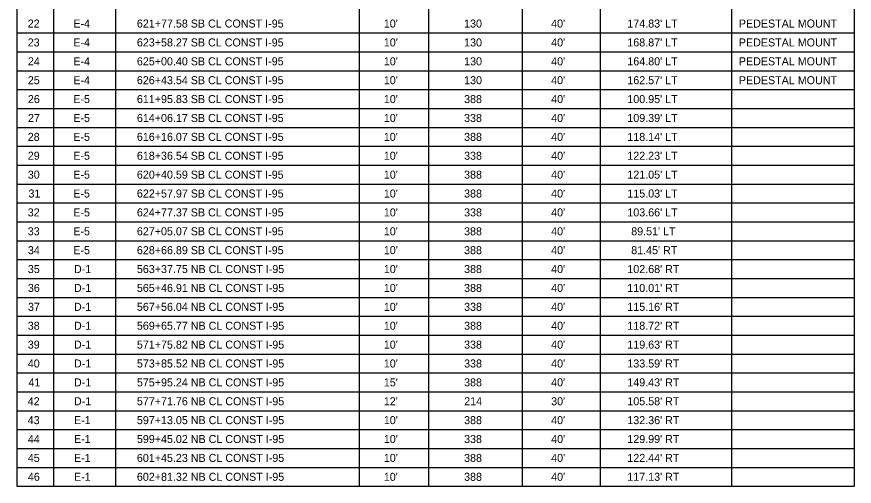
# Model space of a CAD drawing. Extents: x -818.1 to -802.4, y -2221.2 to -2187.7.
# Drawn here: x -817.38 to -810.06, y -2195.94 to -2191.84 of the extents above; entities that cross this region are included whole.
import ezdxf

# ---------------------------------------------------------------- set-up
doc = ezdxf.new("R2010")
doc.units = 0
for name, color, linetype in [('PlotBorder_dp', 7, 'Continuous'), ('SheetBorder_dp', 7, 'Continuous'), ('SheetLines_dp', 7, 'Continuous'), ('TextMinor', 7, 'Continuous')]:
    doc.layers.add(name, color=color, linetype=linetype)

msp = doc.modelspace()

# ---------------------------------------------------------------- linework, layer by layer
at = {"layer": 'PlotBorder_dp'}
for p, q in [((-817.0539, -2188.0217), (-817.0539, -2195.9417)), ((-817.0539, -2188.0217), (-817.0539, -2195.9417)), ((-816.5139, -2188.0217), (-816.5139, -2195.9417)), ((-816.5139, -2188.0217), (-816.5139, -2195.9417)), ((-814.3839, -2188.0217), (-814.3839, -2193.9617)), ((-814.3839, -2188.0217), (-814.3839, -2195.9417)), ((-813.7764, -2188.0217), (-813.7764, -2195.9417)), ((-813.7764, -2188.0217), (-813.7764, -2195.9417)), ((-812.9589, -2188.0217), (-812.9589, -2195.9417)), ((-812.9589, -2188.0217), (-812.9589, -2195.9417)), ((-812.2764, -2188.0217), (-812.2764, -2195.9417)), ((-812.2764, -2188.0217), (-812.2764, -2195.9417)), ((-811.1289, -2188.0217), (-811.1289, -2195.9417)), ((-811.1289, -2188.0217), (-811.1289, -2195.9417)), ((-814.3839, -2194.1267), (-814.3839, -2195.9417))]:
    msp.add_line(p, q, dxfattribs=at)
at = {"layer": 'SheetLines_dp'}
for p, q in [((-817.3764, -2187.6917), (-817.3764, -2195.9417)), ((-810.0564, -2187.6917), (-810.0564, -2195.9417)), ((-810.0564, -2187.6917), (-810.0564, -2195.9417)), ((-817.3764, -2195.9417), (-817.0539, -2195.9417)), ((-817.0539, -2195.9417), (-810.0564, -2195.9417)), ((-816.5139, -2195.9417), (-814.3839, -2195.9417))]:
    msp.add_line(p, q, dxfattribs=at)
at = {"layer": 'TextMinor'}
for p, q in [((-817.3764, -2191.9817), (-810.0564, -2191.9817)), ((-817.3764, -2191.9817), (-810.0564, -2191.9817)), ((-817.3764, -2192.1467), (-810.0564, -2192.1467)), ((-817.3764, -2192.1467), (-810.0564, -2192.1467)), ((-817.3764, -2192.3117), (-810.0564, -2192.3117)), ((-817.3764, -2192.3117), (-810.0564, -2192.3117)), ((-817.3764, -2192.4767), (-810.0564, -2192.4767)), ((-817.3764, -2192.4767), (-810.0564, -2192.4767)), ((-817.3764, -2192.6417), (-810.0564, -2192.6417)), ((-817.3764, -2192.6417), (-810.0564, -2192.6417)), ((-817.3764, -2192.8067), (-810.0564, -2192.8067)), ((-817.3764, -2192.8067), (-810.0564, -2192.8067)), ((-817.3764, -2192.9717), (-810.0564, -2192.9717)), ((-817.3764, -2192.9717), (-810.0564, -2192.9717)), ((-817.3764, -2193.1367), (-810.0564, -2193.1367)), ((-817.3764, -2193.1367), (-810.0564, -2193.1367)), ((-817.3764, -2193.3017), (-810.0564, -2193.3017)), ((-817.3764, -2193.3017), (-810.0564, -2193.3017)), ((-817.3764, -2193.4667), (-810.0564, -2193.4667)), ((-817.3764, -2193.4667), (-810.0564, -2193.4667)), ((-817.3764, -2193.6317), (-810.0564, -2193.6317)), ((-817.3764, -2193.6317), (-810.0564, -2193.6317)), ((-817.3764, -2193.7967), (-810.0564, -2193.7967)), ((-817.3764, -2193.7967), (-810.0564, -2193.7967)), ((-817.3764, -2193.9617), (-810.0564, -2193.9617)), ((-817.3764, -2193.9617), (-810.0564, -2193.9617)), ((-817.3764, -2194.1267), (-816.5139, -2194.1267)), ((-817.3764, -2194.1267), (-810.0564, -2194.1267)), ((-814.3839, -2194.1267), (-810.0564, -2194.1267)), ((-817.3764, -2194.2917), (-810.0564, -2194.2917)), ((-817.3764, -2194.2917), (-810.0564, -2194.2917)), ((-817.3764, -2194.4567), (-810.0564, -2194.4567)), ((-817.3764, -2194.4567), (-810.0564, -2194.4567)), ((-817.3764, -2194.6217), (-810.0564, -2194.6217)), ((-817.3764, -2194.6217), (-810.0564, -2194.6217)), ((-817.3764, -2194.7867), (-810.0564, -2194.7867)), ((-817.3764, -2194.7867), (-810.0564, -2194.7867)), ((-817.3764, -2194.9517), (-810.0564, -2194.9517)), ((-817.3764, -2194.9517), (-810.0564, -2194.9517)), ((-817.3764, -2195.1167), (-810.0564, -2195.1167)), ((-817.3764, -2195.1167), (-810.0564, -2195.1167)), ((-817.3764, -2195.2817), (-810.0564, -2195.2817)), ((-817.3764, -2195.2817), (-810.0564, -2195.2817)), ((-817.3764, -2195.4467), (-810.0564, -2195.4467)), ((-817.3764, -2195.4467), (-810.0564, -2195.4467)), ((-817.3764, -2195.6117), (-810.0564, -2195.6117)), ((-817.3764, -2195.6117), (-810.0564, -2195.6117)), ((-817.3764, -2195.7767), (-816.5139, -2195.7767)), ((-817.3764, -2195.7767), (-810.0564, -2195.7767)), ((-814.3839, -2195.7767), (-810.0564, -2195.7767)), ((-814.3839, -2195.9417), (-812.9589, -2195.9417)), ((-812.2764, -2195.9417), (-810.0564, -2195.9417))]:
    msp.add_line(p, q, dxfattribs=at)

# ---------------------------------------------------------------- texts
at = {"layer": 'SheetBorder_dp'}
for s, p in [('22', (-817.2804, -2191.9342)), ('E-4', (-816.8817, -2191.9342)), ('621+77.58 SB CL CONST I-95', (-816.3263, -2191.9342)), ("10'", (-814.1681, -2191.9342)), ('130', (-813.4662, -2191.9342)), ("40'", (-812.7056, -2191.9342)), ("174.83' LT", (-812.0396, -2191.9342)), ('PEDESTAL MOUNT', (-811.0651, -2191.9342)), ('23', (-817.2804, -2192.0992)), ('E-4', (-816.8817, -2192.0992)), ('623+58.27 SB CL CONST I-95', (-816.3263, -2192.0992)), ("10'", (-814.1681, -2192.0992)), ('130', (-813.4662, -2192.0992)), ("40'", (-812.7056, -2192.0992)), ("168.87' LT", (-812.0396, -2192.0992)), ('PEDESTAL MOUNT', (-811.0651, -2192.0992)), ('24', (-817.279, -2192.2642)), ('625+00.40 SB CL CONST I-95', (-816.3263, -2192.2642)), ("10'", (-814.1681, -2192.2642)), ('130', (-813.4662, -2192.2642)), ("40'", (-812.7056, -2192.2642)), ("164.80' LT", (-812.0396, -2192.2642)), ('PEDESTAL MOUNT', (-811.0651, -2192.2642)), ('E-4', (-816.8817, -2192.2642)), ('25', (-817.2795, -2192.4292)), ('E-4', (-816.8817, -2192.4292)), ('626+43.54 SB CL CONST I-95', (-816.3263, -2192.4292)), ("10'", (-814.1681, -2192.4292)), ('130', (-813.4662, -2192.4292)), ("40'", (-812.7056, -2192.4292)), ("162.57' LT", (-812.0396, -2192.4292)), ('PEDESTAL MOUNT', (-811.0651, -2192.4292)), ('26', (-817.279, -2192.5942)), ('E-5', (-816.8822, -2192.5942)), ('611+95.83 SB CL CONST I-95', (-816.3263, -2192.5942)), ("10'", (-814.1681, -2192.5942)), ('388', (-813.4665, -2192.5942)), ("40'", (-812.7056, -2192.5942)), ("100.95' LT", (-812.0396, -2192.5942)), ('27', (-817.2784, -2192.7592)), ('E-5', (-816.8822, -2192.7592)), ('614+06.17 SB CL CONST I-95', (-816.3263, -2192.7592)), ("10'", (-814.1681, -2192.7592)), ('338', (-813.4665, -2192.7592)), ("40'", (-812.7056, -2192.7592)), ("109.39' LT", (-812.0396, -2192.7592)), ('28', (-817.2802, -2192.9242)), ('E-5', (-816.8822, -2192.9242)), ('616+16.07 SB CL CONST I-95', (-816.3263, -2192.9242)), ("10'", (-814.1681, -2192.9242)), ('388', (-813.4665, -2192.9242)), ("40'", (-812.7056, -2192.9242)), ("118.14' LT", (-812.0396, -2192.9242)), ('29', (-817.28, -2193.0892)), ('E-5', (-816.8822, -2193.0892)), ('618+36.54 SB CL CONST I-95', (-816.3263, -2193.0892)), ("10'", (-814.1681, -2193.0892)), ('338', (-813.4665, -2193.0892)), ("40'", (-812.7056, -2193.0892)), ("122.23' LT", (-812.0396, -2193.0892)), ('30', (-817.2798, -2193.2542)), ('E-5', (-816.8822, -2193.2542)), ('620+40.59 SB CL CONST I-95', (-816.3263, -2193.2542)), ("10'", (-814.1681, -2193.2542)), ('388', (-813.4665, -2193.2542)), ("40'", (-812.7056, -2193.2542)), ("121.05' LT", (-812.0396, -2193.2542)), ('31', (-817.2737, -2193.4192)), ('E-5', (-816.8822, -2193.4192)), ('622+57.97 SB CL CONST I-95', (-816.3263, -2193.4192)), ("10'", (-814.1681, -2193.4192)), ('388', (-813.4665, -2193.4192)), ("40'", (-812.7056, -2193.4192)), ("115.03' LT", (-812.0396, -2193.4192)), ('32', (-817.2804, -2193.5842)), ('E-5', (-816.8822, -2193.5842)), ('624+77.37 SB CL CONST I-95', (-816.3263, -2193.5842)), ("10'", (-814.1681, -2193.5842)), ('338', (-813.4665, -2193.5842)), ("40'", (-812.7056, -2193.5842)), ("103.66' LT", (-812.0396, -2193.5842)), ('33', (-817.2804, -2193.7492)), ('E-5', (-816.8822, -2193.7492)), ('627+05.07 SB CL CONST I-95', (-816.3263, -2193.7492)), ("10'", (-814.1681, -2193.7492)), ('388', (-813.4665, -2193.7492)), ("40'", (-812.7056, -2193.7492)), ("89.51' LT", (-812.0057, -2193.7492)), ('34', (-817.279, -2193.9142)), ('E-5', (-816.8822, -2193.9142)), ('628+66.89 SB CL CONST I-95', (-816.3263, -2193.9142)), ("10'", (-814.1681, -2193.9142)), ('388', (-813.4665, -2193.9142)), ("40'", (-812.7056, -2193.9142)), ("81.45' RT", (-812.0057, -2193.9142)), ('35', (-817.2795, -2194.0792)), ('D-1', (-816.8763, -2194.0792)), ('563+37.75 NB CL CONST I-95', (-816.3263, -2194.0792)), ("10'", (-814.1681, -2194.0792)), ('388', (-813.4665, -2194.0792)), ("40'", (-812.7056, -2194.0792)), ("102.68' RT", (-812.0396, -2194.0792)), ('36', (-817.279, -2194.2442)), ('D-1', (-816.8763, -2194.2442)), ('565+46.91 NB CL CONST I-95', (-816.3263, -2194.2442)), ("10'", (-814.1681, -2194.2442)), ('388', (-813.4665, -2194.2442)), ("40'", (-812.7056, -2194.2442)), ("110.01' RT", (-812.0396, -2194.2442)), ('37', (-817.2784, -2194.4092)), ('D-1', (-816.8763, -2194.4092)), ('567+56.04 NB CL CONST I-95', (-816.3263, -2194.4092)), ("10'", (-814.1681, -2194.4092)), ('338', (-813.4665, -2194.4092)), ("40'", (-812.7056, -2194.4092)), ("115.16' RT", (-812.0396, -2194.4092)), ('38', (-817.2802, -2194.5742)), ('D-1', (-816.8763, -2194.5742)), ('569+65.77 NB CL CONST I-95', (-816.3263, -2194.5742)), ("10'", (-814.1681, -2194.5742)), ('388', (-813.4665, -2194.5742)), ("40'", (-812.7056, -2194.5742)), ("118.72' RT", (-812.0396, -2194.5742)), ('39', (-817.28, -2194.7392)), ('D-1', (-816.8763, -2194.7392)), ('571+75.82 NB CL CONST I-95', (-816.3263, -2194.7392)), ("10'", (-814.1681, -2194.7392)), ('338', (-813.4665, -2194.7392)), ("40'", (-812.7056, -2194.7392)), ("119.63' RT", (-812.0396, -2194.7392)), ('40', (-817.2798, -2194.9042)), ('D-1', (-816.8763, -2194.9042)), ('573+85.52 NB CL CONST I-95', (-816.3263, -2194.9042)), ("10'", (-814.1681, -2194.9042)), ('338', (-813.4665, -2194.9042)), ("40'", (-812.7056, -2194.9042)), ("133.59' RT", (-812.0396, -2194.9042)), ('41', (-817.2737, -2195.0692)), ('D-1', (-816.8763, -2195.0692)), ('575+95.24 NB CL CONST I-95', (-816.3263, -2195.0692)), ("15'", (-814.1681, -2195.0692)), ('388', (-813.4665, -2195.0692)), ("40'", (-812.7056, -2195.0692)), ("149.43' RT", (-812.0396, -2195.0692)), ('42', (-817.2804, -2195.2342)), ('D-1', (-816.8763, -2195.2342)), ('577+71.76 NB CL CONST I-95', (-816.3263, -2195.2342)), ("12'", (-814.1681, -2195.2342)), ('214', (-813.4654, -2195.2342)), ("30'", (-812.7056, -2195.2342)), ("105.58' RT", (-812.0396, -2195.2342)), ('43', (-817.2804, -2195.3992)), ('E-1', (-816.8763, -2195.3992)), ('597+13.05 NB CL CONST I-95', (-816.3263, -2195.3992)), ("10'", (-814.1681, -2195.3992)), ('388', (-813.4665, -2195.3992)), ("40'", (-812.7056, -2195.3992)), ("132.36' RT", (-812.0396, -2195.3992)), ('44', (-817.279, -2195.5642)), ('E-1', (-816.8763, -2195.5642)), ('599+45.02 NB CL CONST I-95', (-816.3263, -2195.5642)), ("10'", (-814.1681, -2195.5642)), ('338', (-813.4665, -2195.5642)), ("40'", (-812.7056, -2195.5642)), ("129.99' RT", (-812.0396, -2195.5642)), ('45', (-817.2795, -2195.7292)), ('E-1', (-816.8763, -2195.7292)), ('601+45.23 NB CL CONST I-95', (-816.3263, -2195.7292)), ("10'", (-814.1681, -2195.7292)), ('388', (-813.4665, -2195.7292)), ("40'", (-812.7056, -2195.7292)), ("122.44' RT", (-812.0396, -2195.7292)), ('46', (-817.279, -2195.8942)), ('E-1', (-816.8763, -2195.8942)), ('602+81.32 NB CL CONST I-95', (-816.3263, -2195.8942)), ("10'", (-814.1681, -2195.8942)), ('388', (-813.4665, -2195.8942)), ("40'", (-812.7056, -2195.8942)), ("117.13' RT", (-812.0396, -2195.8942))]:
    msp.add_text(s, height=0.07, dxfattribs=at).set_placement(p)

doc.saveas('drawing.dxf')
